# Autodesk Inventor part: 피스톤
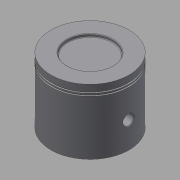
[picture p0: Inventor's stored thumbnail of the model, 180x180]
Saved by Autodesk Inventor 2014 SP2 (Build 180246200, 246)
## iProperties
Created: 2016-11
Part Number: 피스톤
Material: 강철, 탄소
Document SubType Name: Modeling
Designer: mduedu
Density: 7.87 g/cm^3
Mass: 410.128 g
Surface Area: 237.507 cm^2
Volume: 52.1129 cm^3
Appearance: 기본값
Author: mduedu
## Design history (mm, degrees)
sketch "스케치1"
  geometry: C1 r 30 at (0, 0); 1 further point
  constraints: 1 centre point, 1 coincident
  dimensions: "d0" = 60 diameter of C1
extrude "돌출1" new body sketch "스케치1" distance "d1" = 50; taper "d2" = 0 deg
sketch "스케치2"
  geometry: C1 r 28 at (0, 0); 1 further point
  constraints: 1 centre point, 1 coincident
  dimensions: "d3" = 56 diameter of C1
extrude "돌출2" cut sketch "스케치2" distance "d4" = 45; taper "d5" = 0 deg
sketch "스케치3"
  geometry: L1 (30, 0)-(30, 50) reference; L2 (30, 45)-(29, 45); L3 (29, 45)-(29, 44); L4 (29, 44)-(30, 44); L5 (30, 44)-(30, 45); L6 (30, 43)-(29, 43); L7 (29, 43)-(29, 42); L8 (29, 42)-(30, 42); L9 (30, 42)-(30, 43); L10 (30, 50)-(-30, 50) reference; L11 (0, 50)-(0, 0)
  constraints: 18 end point, 4 parallel, 3 equal length, 3 perpendicular, 2 horizontal, 2 point on line, 1 midpoint
  dimensions: "d6" = 1 distance of L2.start L2.end; "d8" = 5 distance between parallel lines of L10 L2; "d9" = 1 distance between parallel lines of L6 L4
revolve "회전1" sketch "스케치3" stored, may be unused: angle "d10" = 90 deg
node "작업 평면1"
sketch "스케치4"
  geometry: L1 (0, -22.978)-(45, -22.978) reference; L2 (45, -22.978)-(45, 22.978) reference; L3 (45, 22.978)-(0, 22.978) reference; L4 (0, 22.978)-(0, 25.377) reference; L5 (0, 25.377)-(42, 25.377) reference; L6 (42, 25.377)-(42, 24.187) reference; L7 (42, 24.187)-(43, 24.187) reference; L8 (43, 24.187)-(43, 25.377) reference; L9 (43, 25.377)-(44, 25.377) reference; L10 (44, 25.377)-(44, 24.187) reference; L11 (44, 24.187)-(45, 24.187) reference; L12 (45, 24.187)-(45, 25.377) reference; L13 (45, 25.377)-(50, 25.377) reference; L14 (50, 25.377)-(50, -25.377) reference; L15 (50, -25.377)-(45, -25.377) reference; L16 (45, -25.377)-(45, -24.187) reference; L17 (45, -24.187)-(44, -24.187) reference; L18 (44, -24.187)-(44, -25.377) reference; L19 (44, -25.377)-(43, -25.377) reference; L20 (43, -25.377)-(43, -24.187) reference; L21 (43, -24.187)-(42, -24.187) reference; L22 (42, -24.187)-(42, -25.377) reference; L23 (42, -25.377)-(0, -25.377) reference; L24 (0, -25.377)-(0, -22.978) reference; L25 (12.5, 22.978)-(45, 22.978); L26 (45, 22.978)-(45, -22.978); L27 (45, -22.978)-(12.5, -22.978); L28 (12.5, -22.978)-(12.5, 22.978); C1 r 7.5 at (20, 0); C2 r 4 at (20, 0); 1 further point
  constraints: 8 end point, 2 centre point, 2 parallel, 1 coincident, 1 horizontal, 1 horizontal alignment, 1 perpendicular, 1 point on line, 1 tangent
  dimensions: "d12" = 15 diameter of C1; "d13" = 8 diameter of C2; "d14" = 20 distance of point (0, 0) C1.centre
  node "절단 모서리 투영1"
extrude "돌출3" join sketch "스케치4" stored distance "d15" = 11.75; taper "d16" = 0 deg
extrude "돌출4" cut sketch "스케치4" stored distance "d17" = 72; taper "d18" = 0 deg
fillet "모깎기2" dims "d20" = 3
chamfer "모따기1" distance "d21" = 0.5; stored, may be unused: second distance "d22" = 2, angle "d23" = 45 deg
chamfer "모따기2" distance "d24" = 0.5; stored, may be unused: second distance "d25" = 2, angle "d26" = 45 deg
sketch "스케치5"
  geometry: C1 r 17.5 at (0, 0); 1 further point
  constraints: 1 centre point, 1 coincident
  dimensions: "d27" = 35 diameter of C1
extrude "돌출5" cut sketch "스케치5" distance "d28" = 2; taper "d29" = 0 deg
fillet "모깎기3" dims "d30" = 0.5
node "솔리드1"
mirror "대칭1"
other parameters: "d11" = -16
